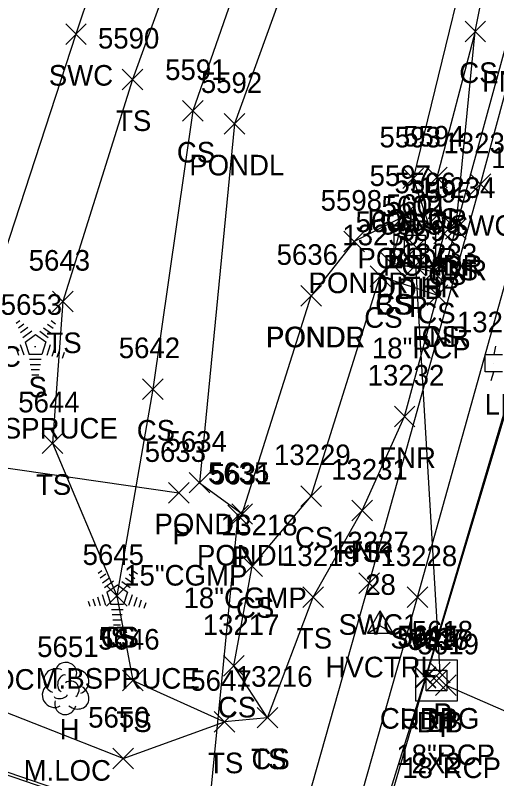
# Model space of a CAD drawing. Extents: x 1462089 to 1464015, y 730534 to 736144.
# Drawn here: x 1462351.3 to 1462398, y 730762 to 730836.1 of the extents above; entities that cross this region are included whole.
import ezdxf

# ---------------------------------------------------------------- set-up
doc = ezdxf.new("R2010")
doc.units = 0
for name, color, linetype in [('C_A', 7, 'Continuous'), ('C_I', 7, 'Continuous'), ('CPSM', 7, 'Continuous'), ('D_A', 7, 'Continuous'), ('D_C', 7, 'Continuous'), ('D_I', 7, 'Continuous'), ('D_TIC', 7, 'Continuous'), ('DCP', 7, 'Continuous'), ('DS', 7, 'Continuous'), ('L_A', 7, 'Continuous'), ('L_C', 7, 'Continuous'), ('L_I', 7, 'Continuous'), ('L_TIC', 7, 'Continuous'), ('LAWE', 7, 'Continuous'), ('LELB', 7, 'Continuous'), ('LFNC', 7, 'Continuous'), ('LTC', 7, 'Continuous'), ('LTD', 7, 'Continuous'), ('P_A', 7, 'Continuous'), ('P_I', 7, 'Continuous'), ('P_TIC', 7, 'Continuous'), ('PET', 7, 'Continuous'), ('R_A', 7, 'Continuous'), ('R_I', 7, 'Continuous'), ('R_TIC', 7, 'Continuous'), ('RC', 7, 'Continuous'), ('RDP', 7, 'Continuous'), ('RSW', 7, 'Continuous'), ('U_A', 7, 'Continuous'), ('U_I', 7, 'Continuous'), ('ULP', 7, 'Continuous')]:
    doc.layers.add(name, color=color, linetype=linetype)

msp = doc.modelspace()

# ---------------------------------------------------------------- linework, layer by layer
at = {"layer": 'CPSM'}
for p, q in [((1462385.472, 730776.12), (1462386.722, 730778.285)), ((1462387.972, 730776.12), (1462386.722, 730778.285)), ((1462386.722, 730776.841), (1462386.722, 730778.285)), ((1462385.472, 730776.12), (1462386.722, 730776.841)), ((1462386.722, 730776.841), (1462386.722, 730776.841)), ((1462386.722, 730776.841), (1462387.972, 730776.12)), ((1462385.472, 730776.12), (1462387.972, 730776.12))]:
    msp.add_line(p, q, dxfattribs=at)
at = {"layer": 'D_TIC'}
for points in [[(1462389.223, 730812.555), (1462391.223, 730814.555)], [(1462391.223, 730812.555), (1462389.223, 730814.555)], [(1462389.141, 730810.792), (1462391.141, 730812.792)], [(1462391.141, 730810.792), (1462389.141, 730812.792)], [(1462366.196, 730788.743), (1462368.196, 730790.743)], [(1462368.196, 730788.743), (1462366.196, 730790.743)], [(1462371.952, 730786.555), (1462373.952, 730788.555)], [(1462373.952, 730786.555), (1462371.952, 730788.555)], [(1462391.505, 730771.322), (1462393.505, 730773.322)], [(1462393.505, 730771.322), (1462391.505, 730773.322)], [(1462391.163, 730770.494), (1462393.163, 730772.494)], [(1462393.163, 730770.494), (1462391.163, 730772.494)], [(1462392.082, 730770.069), (1462394.082, 730772.069)], [(1462394.082, 730770.069), (1462392.082, 730772.069)]]:
    msp.add_lwpolyline(points, dxfattribs=at)
at = {"layer": 'DCP'}
for points in [[(1462390.141, 730811.792), (1462392.505, 730772.322)], [(1462307.757, 730798.341), (1462367.196, 730789.743)], [(1462369.475, 730752.081), (1462372.952, 730787.555)], [(1462393.082, 730771.069), (1462433.543, 730753.417)]]:
    msp.add_lwpolyline(points, dxfattribs=at)
at = {"layer": 'DS'}
for p, q in [((1462388.072, 730815.729), (1462392.072, 730815.729)), ((1462388.072, 730811.729), (1462388.083, 730815.729)), ((1462392.072, 730815.729), (1462392.072, 730811.729)), ((1462389.072, 730814.729), (1462391.072, 730814.729)), ((1462389.072, 730812.729), (1462389.072, 730814.729)), ((1462391.072, 730814.729), (1462391.072, 730812.729)), ((1462390.075, 730813.739), (1462390.075, 730813.739)), ((1462391.072, 730812.729), (1462389.072, 730812.729)), ((1462392.072, 730811.729), (1462388.072, 730811.729)), ((1462390.572, 730811.729), (1462391.072, 730811.729)), ((1462390.181, 730773.528), (1462394.181, 730773.528)), ((1462390.181, 730769.528), (1462390.181, 730773.528)), ((1462394.181, 730773.528), (1462394.181, 730769.528)), ((1462391.181, 730770.528), (1462391.181, 730772.528)), ((1462391.181, 730772.528), (1462393.181, 730772.528)), ((1462393.181, 730772.528), (1462393.181, 730770.528)), ((1462392.187, 730771.529), (1462392.187, 730771.529)), ((1462392.187, 730771.529), (1462392.187, 730771.529)), ((1462393.181, 730770.528), (1462391.181, 730770.528)), ((1462394.181, 730769.528), (1462390.181, 730769.528))]:
    msp.add_line(p, q, dxfattribs=at)
at = {"layer": 'L_TIC'}
for points in [[(1462394.937, 730833.507), (1462396.937, 730835.507)], [(1462396.937, 730833.507), (1462394.937, 730835.507)], [(1462361.703, 730828.846), (1462363.703, 730830.846)], [(1462363.703, 730828.846), (1462361.703, 730830.846)], [(1462367.564, 730825.791), (1462369.564, 730827.791)], [(1462369.564, 730825.791), (1462367.564, 730827.791)], [(1462371.587, 730824.537), (1462373.587, 730826.537)], [(1462373.587, 730824.537), (1462371.587, 730826.537)], [(1462388.908, 730819.254), (1462390.908, 730821.254)], [(1462390.908, 730819.254), (1462388.908, 730821.254)], [(1462391.196, 730819.343), (1462393.196, 730821.343)], [(1462393.196, 730819.343), (1462391.196, 730821.343)], [(1462387.945, 730815.51), (1462389.945, 730817.51)], [(1462389.945, 730815.51), (1462387.945, 730817.51)], [(1462387.945, 730815.51), (1462389.945, 730817.51)], [(1462389.945, 730815.51), (1462387.945, 730817.51)], [(1462390.412, 730814.802), (1462392.412, 730816.802)], [(1462392.412, 730814.802), (1462390.412, 730816.802)], [(1462391.921, 730813.91), (1462393.921, 730815.91)], [(1462393.921, 730813.91), (1462391.921, 730815.91)], [(1462393.046, 730814.355), (1462395.046, 730816.355)], [(1462395.046, 730814.355), (1462393.046, 730816.355)], [(1462393.046, 730814.355), (1462395.046, 730816.355)], [(1462395.046, 730814.355), (1462393.046, 730816.355)], [(1462383.205, 730813.114), (1462385.205, 730815.114)], [(1462385.205, 730813.114), (1462383.205, 730815.114)], [(1462386.796, 730811.037), (1462388.796, 730813.037)], [(1462388.796, 730811.037), (1462386.796, 730813.037)], [(1462386.796, 730811.037), (1462388.796, 730813.037)], [(1462388.796, 730811.037), (1462386.796, 730813.037)], [(1462390.869, 730810.191), (1462392.869, 730812.191)], [(1462392.869, 730810.191), (1462390.869, 730812.191)], [(1462385.729, 730809.756), (1462387.729, 730811.756)], [(1462387.729, 730809.756), (1462385.729, 730811.756)], [(1462354.952, 730807.297), (1462356.952, 730809.297)], [(1462356.952, 730807.297), (1462354.952, 730809.297)], [(1462379.039, 730807.86), (1462381.039, 730809.86)], [(1462381.039, 730807.86), (1462379.039, 730809.86)], [(1462379.039, 730807.86), (1462381.039, 730809.86)], [(1462381.039, 730807.86), (1462379.039, 730809.86)], [(1462391.276, 730807.912), (1462393.276, 730809.912)], [(1462393.276, 730807.912), (1462391.276, 730809.912)], [(1462391.276, 730807.912), (1462393.276, 730809.912)], [(1462393.276, 730807.912), (1462391.276, 730809.912)], [(1462363.679, 730798.81), (1462365.679, 730800.81)], [(1462365.679, 730798.81), (1462363.679, 730800.81)], [(1462388.087, 730796.155), (1462390.087, 730798.155)], [(1462390.087, 730796.155), (1462388.087, 730798.155)], [(1462353.939, 730793.546), (1462355.939, 730795.546)], [(1462355.939, 730793.546), (1462353.939, 730795.546)], [(1462368.213, 730789.727), (1462370.213, 730791.727)], [(1462370.213, 730789.727), (1462368.213, 730791.727)], [(1462379.016, 730788.43), (1462381.016, 730790.43)], [(1462381.016, 730788.43), (1462379.016, 730790.43)], [(1462372.33, 730786.689), (1462374.33, 730788.689)], [(1462374.33, 730786.689), (1462372.33, 730788.689)], [(1462383.981, 730787.027), (1462385.981, 730789.027)], [(1462385.981, 730787.027), (1462383.981, 730789.027)], [(1462383.981, 730787.027), (1462385.981, 730789.027)], [(1462385.981, 730787.027), (1462383.981, 730789.027)], [(1462373.293, 730781.615), (1462375.293, 730783.615)], [(1462375.293, 730781.615), (1462373.293, 730783.615)], [(1462360.177, 730778.741), (1462362.177, 730780.741)], [(1462362.177, 730778.741), (1462360.177, 730780.741)], [(1462360.177, 730778.741), (1462362.177, 730780.741)], [(1462362.177, 730778.741), (1462360.177, 730780.741)], [(1462379.228, 730778.633), (1462381.228, 730780.633)], [(1462381.228, 730778.633), (1462379.228, 730780.633)], [(1462371.54, 730771.949), (1462373.54, 730773.949)], [(1462373.54, 730771.949), (1462371.54, 730773.949)], [(1462361.749, 730770.532), (1462363.749, 730772.532)], [(1462363.749, 730770.532), (1462361.749, 730772.532)], [(1462370.615, 730766.536), (1462372.615, 730768.536)], [(1462372.615, 730766.536), (1462370.615, 730768.536)], [(1462374.796, 730766.927), (1462376.796, 730768.927)], [(1462376.796, 730766.927), (1462374.796, 730768.927)], [(1462374.796, 730766.927), (1462376.796, 730768.927)], [(1462376.796, 730766.927), (1462374.796, 730768.927)], [(1462360.801, 730762.964), (1462362.801, 730764.964)], [(1462362.801, 730762.964), (1462360.801, 730764.964)]]:
    msp.add_lwpolyline(points, dxfattribs=at)
at = {"layer": 'LAWE'}
for points in [[(1462386.109, 730862.93), (1462372.587, 730825.537), (1462369.213, 730790.727), (1462373.33, 730787.689), (1462380.039, 730808.86)], [(1462397.586, 730851.638), (1462389.908, 730820.254), (1462391.412, 730815.802), (1462388.945, 730816.51), (1462384.205, 730814.114), (1462380.039, 730808.86)]]:
    msp.add_lwpolyline(points, dxfattribs=at)
at = {"layer": 'LELB'}
for points in [[(1462385.599, 730896.171), (1462375.995, 730866.528), (1462362.703, 730829.846), (1462355.952, 730808.297), (1462354.939, 730794.546), (1462361.177, 730779.741), (1462362.749, 730771.532), (1462371.615, 730767.536)], [(1462393.773, 730896.111), (1462381.885, 730865.173), (1462368.564, 730826.791), (1462364.679, 730799.81), (1462361.177, 730779.741)], [(1462394.046, 730815.355), (1462395.937, 730834.507), (1462398.451, 730847.089), (1462399.649, 730852.585), (1462403.428, 730862.197), (1462408.792, 730879.002)], [(1462395.937, 730834.507), (1462392.196, 730820.343)], [(1462392.196, 730820.343), (1462392.921, 730814.91), (1462391.869, 730811.191), (1462387.796, 730812.037)], [(1462388.945, 730816.51), (1462387.796, 730812.037)], [(1462386.729, 730810.756), (1462387.796, 730812.037)], [(1462375.796, 730767.927), (1462372.54, 730772.949), (1462374.293, 730782.615), (1462380.016, 730789.43), (1462386.729, 730810.756), (1462392.276, 730808.912)], [(1462375.796, 730767.927), (1462380.228, 730779.633), (1462384.981, 730788.027)], [(1462361.801, 730763.964), (1462346.34, 730770.052)], [(1462375.796, 730767.927), (1462371.615, 730767.536)], [(1462361.801, 730763.964), (1462371.615, 730767.536)]]:
    msp.add_lwpolyline(points, dxfattribs=at)
at = {"layer": 'LFNC'}
msp.add_lwpolyline([(1462384.981, 730788.027), (1462389.087, 730797.155), (1462392.276, 730808.912), (1462394.046, 730815.355), (1462399.051, 730833.672), (1462400.215, 730843.197), (1462401.341, 730846.491), (1462402.735, 730851.199), (1462406.71, 730861.133), (1462411.72, 730877.945), (1462422.89, 730920.747), (1462428.81, 730945.275), (1462429.663, 730954.758)], dxfattribs=at)
at = {"layer": 'LTC'}
for p, q in [((1462351.436, 730806.219), (1462351.79, 730806.476)), ((1462354.834, 730806.459), (1462355.253, 730806.154)), ((1462351.645, 730805.753), (1462352.174, 730806.137)), ((1462351.855, 730805.287), (1462352.559, 730805.799)), ((1462354.092, 730805.762), (1462354.771, 730805.269)), ((1462354.463, 730806.111), (1462355.012, 730805.711)), ((1462352.064, 730804.821), (1462352.943, 730805.459)), ((1462352.289, 730804.366), (1462353.301, 730805.101)), ((1462353.301, 730805.101), (1462354.298, 730804.376)), ((1462353.721, 730805.414), (1462354.53, 730804.825)), ((1462351.834, 730804.147), (1462352.165, 730803.128)), ((1462352.289, 730804.366), (1462352.676, 730803.173)), ((1462354.298, 730804.376), (1462353.907, 730803.173)), ((1462354.735, 730804.105), (1462354.397, 730803.066)), ((1462351.379, 730803.931), (1462351.65, 730803.096)), ((1462355.18, 730803.855), (1462354.892, 730802.97)), ((1462355.624, 730803.605), (1462355.387, 730802.875)), ((1462356.069, 730803.354), (1462355.882, 730802.78)), ((1462353.907, 730803.173), (1462352.676, 730803.173)), ((1462353.868, 730802.673), (1462352.724, 730802.673)), ((1462353.784, 730802.173), (1462352.796, 730802.173)), ((1462353.701, 730801.673), (1462352.869, 730801.673)), ((1462353.617, 730801.173), (1462352.942, 730801.173)), ((1462359.372, 730781.949), (1462359.727, 730782.206)), ((1462359.582, 730781.483), (1462360.111, 730781.868)), ((1462362.399, 730781.841), (1462362.949, 730781.442)), ((1462362.77, 730782.189), (1462363.19, 730781.885)), ((1462359.791, 730781.018), (1462360.495, 730781.529)), ((1462360.001, 730780.552), (1462360.879, 730781.19)), ((1462361.657, 730781.144), (1462362.467, 730780.556)), ((1462362.028, 730781.493), (1462362.707, 730780.999)), ((1462360.225, 730780.097), (1462361.237, 730780.831)), ((1462361.237, 730780.831), (1462362.234, 730780.106)), ((1462359.315, 730779.661), (1462359.587, 730778.826)), ((1462359.771, 730779.878), (1462360.102, 730778.858)), ((1462360.225, 730780.097), (1462360.612, 730778.903)), ((1462362.234, 730780.106), (1462361.843, 730778.903)), ((1462362.672, 730779.836), (1462362.334, 730778.796)), ((1462363.116, 730779.585), (1462362.829, 730778.701)), ((1462358.405, 730779.228), (1462358.557, 730778.76)), ((1462358.86, 730779.445), (1462359.072, 730778.793)), ((1462361.843, 730778.903), (1462360.612, 730778.903)), ((1462363.561, 730779.335), (1462363.324, 730778.606)), ((1462364.005, 730779.085), (1462363.818, 730778.511)), ((1462361.805, 730778.403), (1462360.66, 730778.403)), ((1462361.721, 730777.903), (1462360.732, 730777.903)), ((1462361.637, 730777.403), (1462360.805, 730777.403)), ((1462361.553, 730776.903), (1462360.878, 730776.903))]:
    msp.add_line(p, q, dxfattribs=at)
at = {"layer": 'LTD'}
msp.add_line((1462356.205, 730770.812), (1462356.205, 730770.812), dxfattribs=at)
msp.add_line((1462356.205, 730770.812), (1462356.205, 730770.812), dxfattribs=at)
msp.add_arc((1462356.251, 730772.246), 1.047, 335.52715, 180.95627, dxfattribs=at)
for centre, major_axis, ratio, start_param, end_param in [((1462355.413, 730771.478), (1.21, -0.512), 0.895232, 1.570796, 4.712389), ((1462357.246, 730771.395), (-1.141, -0.483), 0.949671, 1.570796, 4.712389), ((1462355.996, 730771.27), (-0.208, -0.792), 0.645439, 3.141593, 6.283185), ((1462356.705, 730770.645), (-0.5, 0.667), 0.989748, 3.141593, 6.283185), ((1462355.121, 730770.103), (0.584, -1.042), 0.959034, 3.141593, 6.283185), ((1462357.205, 730769.979), (-1.09, 0.792), 0.841452, 1.570796, 4.712389), ((1462355.746, 730770.062), (-0.625, -0.083), 0.423636, 0, 3.141593), ((1462356.205, 730769.312), (0.265, 1.061), 0.942809, 1.570796, 4.712389)]:
    msp.add_ellipse(centre, major_axis=major_axis, ratio=ratio, start_param=start_param, end_param=end_param, dxfattribs=at)
at = {"layer": 'P_TIC'}
for points in [[(1462390.124, 730770.788), (1462392.124, 730772.788)], [(1462392.124, 730770.788), (1462390.124, 730772.788)]]:
    msp.add_lwpolyline(points, dxfattribs=at)
at = {"layer": 'PET'}
msp.add_lwpolyline([(1462468.326, 731055.464), (1462454.623, 731002.71), (1462439.372, 730943.541), (1462426.72, 730893.883), (1462414.129, 730848.032), (1462402.675, 730810.272), (1462391.124, 730771.788), (1462384.959, 730750.701), (1462383.455, 730746.117), (1462378.837, 730730.43)], dxfattribs=at)
at = {"layer": 'R_TIC'}
for points in [[(1462356.229, 730833.247), (1462358.229, 730835.247)], [(1462358.229, 730833.247), (1462356.229, 730835.247)], [(1462395.441, 730818.679), (1462397.441, 730820.679)], [(1462397.441, 730818.679), (1462395.441, 730820.679)], [(1462384.645, 730779.966), (1462386.645, 730781.966)], [(1462386.645, 730779.966), (1462384.645, 730781.966)], [(1462389.334, 730778.631), (1462391.334, 730780.631)], [(1462391.334, 730778.631), (1462389.334, 730780.631)], [(1462390.106, 730770.86), (1462392.106, 730772.86)], [(1462392.106, 730770.86), (1462390.106, 730772.86)]]:
    msp.add_lwpolyline(points, dxfattribs=at)
at = {"layer": 'RC'}
for points in [[(1462468.059, 731055.45), (1462454.452, 731002.687), (1462439.295, 730943.639), (1462426.445, 730893.892), (1462413.944, 730848.157), (1462402.505, 730810.311), (1462391.106, 730771.86), (1462384.598, 730751.001)], [(1462371.683, 730755.39), (1462344.759, 730764.606)]]:
    msp.add_lwpolyline(points, dxfattribs=at)
at = {"layer": 'RDP'}
msp.add_lwpolyline([(1462371.552, 730755.148), (1462344.722, 730764.348)], dxfattribs=at)
at = {"layer": 'RSW'}
for points in [[(1462365.212, 730706.592), (1462365.681, 730709.782), (1462367.075, 730715.114), (1462375.579, 730745.466), (1462378.85, 730756.938), (1462385.645, 730780.966), (1462396.441, 730819.679), (1462403.544, 730845.945), (1462401.341, 730846.491), (1462400.759, 730846.71), (1462402.181, 730851.525), (1462402.735, 730851.199), (1462404.924, 730850.627), (1462415.031, 730885.133), (1462424.083, 730920.735), (1462432.259, 730954.615), (1462438.298, 730978.946), (1462452.958, 731038.493), (1462460.269, 731066.266), (1462471.187, 731084.223), (1462474.186, 731089.34), (1462475.994, 731088.665), (1462476.765, 731088.455)], [(1462369.056, 730705.4), (1462369.741, 730708.321), (1462371.303, 730712.905), (1462380.074, 730743.761), (1462383.54, 730755.608), (1462390.334, 730779.631), (1462401.128, 730818.25), (1462408.876, 730846.655), (1462419.305, 730882.825), (1462428.728, 730919.268), (1462437.082, 730953.461), (1462442.756, 730977.862), (1462457.49, 731036.904), (1462465.003, 731064.856), (1462473.693, 731078.831), (1462474.261, 731078.765), (1462476.765, 731088.455)], [(1462360.888, 730873.256), (1462369.352, 730870.51), (1462357.229, 730834.247), (1462348.291, 730806.973), (1462337.1, 730773.244), (1462346.34, 730770.052), (1462344.759, 730764.606)]]:
    msp.add_lwpolyline(points, dxfattribs=at)
at = {"layer": 'ULP'}
for p, q in [((1462397.905, 730803.981), (1462397.739, 730803.148)), ((1462396.905, 730801.481), (1462396.905, 730803.148)), ((1462396.905, 730803.148), (1462398.572, 730803.148)), ((1462397.739, 730802.315), (1462397.739, 730802.315)), ((1462398.572, 730801.481), (1462396.905, 730801.481)), ((1462397.489, 730800.648), (1462397.739, 730801.481))]:
    msp.add_line(p, q, dxfattribs=at)

# ---------------------------------------------------------------- texts
at = {"layer": 'C_A'}
msp.add_text('HVCTRL', height=2, dxfattribs=at).set_placement((1462381.415, 730771.841))
at = {"layer": 'C_I'}
msp.add_text('28', height=2, dxfattribs=at).set_placement((1462385.257, 730779.841))
at = {"layer": 'D_A'}
for s, p in [('DITHR', (1462386.32, 730808.707)), ('DIB', (1462388.325, 730808.555)), ('P', (1462389.519, 730806.792)), ('P', (1462366.574, 730784.743)), ('P', (1462372.33, 730782.555)), ('P', (1462391.883, 730767.322)), ('DIB', (1462390.266, 730766.494)), ('DI', (1462391.242, 730766.529)), ('P', (1462392.46, 730766.069))]:
    msp.add_text(s, height=2, dxfattribs=at).set_placement(p)
at = {"layer": 'D_C'}
for s, p in [('18"RCP', (1462385.913, 730802.792)), ('15"CGMP', (1462361.897, 730780.743)), ('18"CGMP', (1462367.653, 730778.555)), ('18"RCP', (1462388.277, 730763.322)), ('18"RCP', (1462388.854, 730762.069)), ('2X2', (1462389.761, 730762.529))]:
    msp.add_text(s, height=2, dxfattribs=at).set_placement(p)
at = {"layer": 'D_I'}
for s, p in [('5602', (1462386.837, 730816.555)), ('5601', (1462387.272, 730816.707)), ('5603', (1462386.756, 730814.792)), ('5633', (1462363.889, 730792.743)), ('5631', (1462370.212, 730790.555)), ('5618', (1462389.765, 730775.322)), ('5616', (1462389.391, 730774.529)), ('5617', (1462389.423, 730774.494)), ('5619', (1462390.334, 730774.069))]:
    msp.add_text(s, height=2, dxfattribs=at).set_placement(p)
at = {"layer": 'L_A'}
for s, p in [('CS', (1462394.378, 730829.507)), ('FNR', (1462396.587, 730828.672)), ('TS', (1462361.113, 730824.846)), ('CS', (1462367.005, 730821.791)), ('PONDL', (1462368.209, 730820.537)), ('CS', (1462390.637, 730815.343)), ('PONDR', (1462385.475, 730815.254)), ('PONDR', (1462384.512, 730811.51)), ('BS', (1462387.386, 730811.51)), ('PONDR', (1462386.979, 730810.802)), ('FNR', (1462391.582, 730810.355)), ('CS', (1462392.487, 730810.355)), ('CS', (1462391.362, 730809.91)), ('PONDR', (1462379.772, 730809.114)), ('CS', (1462386.237, 730807.037)), ('BS', (1462386.237, 730807.037)), ('CS', (1462385.17, 730805.756)), ('CS', (1462390.31, 730806.191)), ('PONDR', (1462375.606, 730803.86)), ('PONDL', (1462375.661, 730803.86)), ('FNR', (1462389.812, 730803.912)), ('CS', (1462390.717, 730803.912)), ('TS', (1462354.362, 730803.297)), ('S', (1462352.626, 730799.01)), ('CS', (1462363.12, 730794.81)), ('FNR', (1462386.622, 730792.155)), ('TS', (1462353.348, 730789.546)), ('PONDL', (1462364.835, 730785.727)), ('CS', (1462378.457, 730784.43)), ('FNR', (1462382.516, 730783.027)), ('TS', (1462383.39, 730783.027)), ('PONDL', (1462368.952, 730782.689)), ('CS', (1462372.734, 730777.615)), ('TS', (1462359.586, 730774.741)), ('CS', (1462359.618, 730774.741)), ('S', (1462360.563, 730774.741)), ('TS', (1462378.637, 730774.633)), ('CS', (1462370.981, 730767.949)), ('TS', (1462361.159, 730766.532)), ('H', (1462355.638, 730765.812)), ('TS', (1462374.205, 730762.927)), ('CS', (1462374.237, 730762.927)), ('TS', (1462370.025, 730762.536))]:
    msp.add_text(s, height=2, dxfattribs=at).set_placement(p)
at = {"layer": 'L_C'}
for s, p in [('M.BSPRUCE', (1462345.382, 730795.01)), ('M.LOC', (1462344.748, 730770.638)), ('M.BSPRUCE', (1462353.319, 730770.741)), ('M.LOC', (1462352.15, 730761.812))]:
    msp.add_text(s, height=2, dxfattribs=at).set_placement(p)
at = {"layer": 'L_I'}
for s, p in [('5590', (1462359.357, 730832.846)), ('5591', (1462365.871, 730829.791)), ('5592', (1462369.327, 730828.537)), ('5593', (1462386.648, 730823.254)), ('5594', (1462388.937, 730823.343)), ('5597', (1462385.686, 730819.51)), ('5597', (1462385.686, 730819.51)), ('5596', (1462388.097, 730818.802)), ('13234', (1462390.456, 730818.355)), ('13234', (1462390.456, 730818.355)), ('5595', (1462389.661, 730817.91)), ('5598', (1462380.945, 730817.114)), ('5600', (1462384.324, 730815.037)), ('5600', (1462384.324, 730815.037)), ('5599', (1462388.602, 730814.191)), ('13230', (1462383.052, 730813.756)), ('5636', (1462376.677, 730811.86)), ('5636', (1462376.677, 730811.86)), ('13233', (1462388.686, 730811.912)), ('13233', (1462388.686, 730811.912)), ('5643', (1462352.645, 730811.297)), ('5653', (1462349.933, 730807.01)), ('5642', (1462361.372, 730802.81)), ('13232', (1462385.496, 730800.155)), ('5644', (1462351.632, 730797.546)), ('5634', (1462365.906, 730793.727)), ('13229', (1462376.418, 730792.43)), ('13231', (1462381.957, 730791.027)), ('13231', (1462381.957, 730791.027)), ('5635', (1462370.023, 730790.689)), ('13218', (1462371.27, 730785.615)), ('5645', (1462357.87, 730782.741)), ('5645', (1462357.87, 730782.741)), ('5645', (1462357.87, 730782.741)), ('13219', (1462377.197, 730782.633)), ('13217', (1462369.517, 730775.949)), ('5646', (1462359.387, 730774.532)), ('5651', (1462353.465, 730773.812)), ('13216', (1462372.717, 730770.927)), ('13216', (1462372.717, 730770.927)), ('5647', (1462368.308, 730770.536)), ('5650', (1462358.407, 730766.964))]:
    msp.add_text(s, height=2, dxfattribs=at).set_placement(p)
at = {"layer": 'LTC'}
for p in [(1462353.183, 730804.114), (1462361.12, 730779.845)]:
    msp.add_text('.', height=1.037, rotation=270, dxfattribs=at).set_placement(p)
at = {"layer": 'P_A'}
msp.add_text('RDP', height=2, dxfattribs=at).set_placement((1462388.612, 730766.788))
at = {"layer": 'P_I'}
msp.add_text('5614', height=2, dxfattribs=at).set_placement((1462388.384, 730774.788))
at = {"layer": 'R_A'}
for s, p in [('SWC', (1462354.591, 730829.247)), ('SWC1', (1462393.48, 730814.679)), ('SWC', (1462345.653, 730801.973)), ('SWC1', (1462382.684, 730775.966)), ('SWC', (1462387.696, 730774.631)), ('CURBG', (1462386.689, 730766.86))]:
    msp.add_text(s, height=2, dxfattribs=at).set_placement(p)
at = {"layer": 'R_I'}
for s, p in [('13237', (1462392.851, 730822.679)), ('13236', (1462397.483, 730821.25)), ('13227', (1462382.055, 730783.966)), ('13228', (1462386.743, 730782.631)), ('5615', (1462388.366, 730774.86))]:
    msp.add_text(s, height=2, dxfattribs=at).set_placement(p)
at = {"layer": 'U_A'}
msp.add_text('LI', height=2, dxfattribs=at).set_placement((1462396.841, 730797.315))
at = {"layer": 'U_I'}
msp.add_text('13235', height=2, dxfattribs=at).set_placement((1462394.148, 730805.315))

doc.saveas('drawing.dxf')
